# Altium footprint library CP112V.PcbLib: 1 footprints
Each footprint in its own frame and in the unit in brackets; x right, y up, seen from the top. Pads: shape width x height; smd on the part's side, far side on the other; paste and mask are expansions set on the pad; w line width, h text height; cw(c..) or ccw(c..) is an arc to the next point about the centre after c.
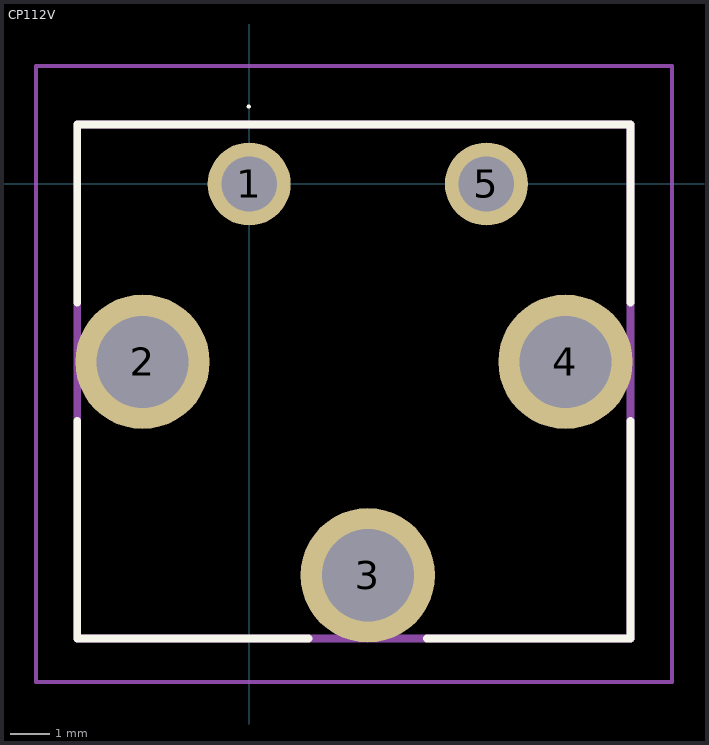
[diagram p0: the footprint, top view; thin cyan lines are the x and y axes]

## CP112V [mm]
pads (5):
  round 2.1 hole 1.4: 1(0,0) 5(6,0)
  round 3.4 hole 2.33: 2(-2.7,-4.5) 3(3,-9.9) 4(8,-4.5)
Top Overlay:
  lines w0.053: 0.014,1.956 cw(c-0.012,1.956) -0.038,1.956 cw(c-0.012,1.956) 0.014,1.956 ; 0.014,1.956 0.014,1.956 ; -0.039,1.956 -0.039,1.956
  lines w0.2: -4.35,-6 -4.35,-11.5 1.5,-11.5 ; -4.35,-3 -4.35,1.5 9.65,1.5 9.65,-3 ; 4.5,-11.5 9.5,-11.5 9.65,-11.5 9.65,-6
Mechanical 15:
  lines w0.2: -4.35,-11.5 9.65,-11.5 9.65,1.5 -4.35,1.5 -4.35,-11.5
Mechanical 20:
  lines w0.1: -5.399,-12.6 10.7,-12.6 10.7,2.983 -5.399,2.983 -5.399,-12.6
